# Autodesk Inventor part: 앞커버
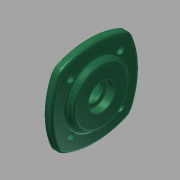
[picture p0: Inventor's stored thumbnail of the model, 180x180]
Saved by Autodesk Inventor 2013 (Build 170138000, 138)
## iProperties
Created: 2015-11
Part Number: 앞커버
Material: 일반
Document SubType Name: Modeling
Designer: mduedu
Density: 2.71 g/cm^3
Author: mduedu
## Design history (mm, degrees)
sketch "스케치1"
  geometry: L1 (50, 50)-(-50, 50); L2 (-50, 50)-(-50, -50); L3 (-50, -50)-(50, -50); L4 (50, -50)-(50, 50); L5 (0, 50)-(0, -50); L6 (50, 0)-(-50, 0); A1 r 90 centre (-40, 0) between (40.415, -40.415) and (40.415, 40.415); A2 r 90 centre (40, 0) between (-40.415, 40.415) and (-40.415, -40.415); A3 r 90 centre (0, -40) between (40.415, 40.415) and (-40.415, 40.415); A4 r 90 centre (0, 40) between (-40.415, -40.415) and (40.415, -40.415); 2 further points
  constraints: 12 end point, 8 point on circle, 5 midpoint, 4 centre point, 2 horizontal alignment, 2 parallel, 2 perpendicular, 2 symmetric about line, 2 tangent, 2 vertical alignment, 1 equal radius, 1 horizontal, 2 other
  dimensions: "d0" = 100 distance of L3.end L1.start; "d2" = 90 radius of A1
extrude "돌출1" new body sketch "스케치1" distance "d3" = 8; taper "d4" = 0 deg
sketch "스케치2"
  geometry: C1 r 35 at (0, 0); 1 further point
  constraints: 1 centre point, 1 coincident
  dimensions: "d5" = 70 diameter of C1
extrude "돌출2" join sketch "스케치2" distance "d6" = 7; taper "d7" = -30 deg
sketch "스케치3"
  geometry: L1 (0, 0)-(0, 40); L2 (0, 0)-(-28.284, 28.284); A1 r 40 centre (0, 0) between (0, 40) and (-28.284, 28.284); 2 further points
  constraints: 4 end point, 2 coincident, 2 point on circle, 1 centre point, 1 vertical
  dimensions: "d8" = 80 diameter of A1; "d9" = 45 deg angle of L1 L2
hole "구멍1" sketch "스케치3" at (-28.284, 28.284) diameter "d11" = 4.5; stored, may be unused: countersink angle "d15" = 90 deg, drill point angle "d17" = 118 deg; dims "d12" = 6, "d13" = 8, "d14" = 4.4, "d16" = 8
sketch "스케치4"
  geometry: C1 r 35 at (0, 0); 1 further point
  constraints: 1 centre point, 1 coincident
  dimensions: "d21" = 70 diameter of C1
extrude "돌출3" join sketch "스케치4" distance "d23" = 12; taper "d24" = 0 deg
hole "구멍2" diameter "d27" = 30; stored, may be unused: countersink angle "d31" = 90 deg, drill point angle "d33" = 0 deg; dims "d25" = 10, "d26" = 10, "d28" = 6, "d29" = 40, "d30" = 12, "d32" = 15
fillet "모깎기2" dims "d35" = 15
fillet "모깎기3" dims "d36" = 3
fillet "모깎기4" dims "d37" = 3
fillet "모깎기5" dims "d38" = 0.3
chamfer "모따기1" distance "d39" = 1; stored, may be unused: second distance "d40" = 2, angle "d41" = 45 deg
hole "구멍3" diameter "d44" = 20; stored, may be unused: countersink angle "d48" = 90 deg, drill point angle "d50" = 118 deg; dims "d45" = 6, "d46" = 30, "d47" = 8.7, "d49" = 8, "d55" = 10, "d56" = 10
fillet "모깎기6" dims "d51" = 0.3
chamfer "모따기2" distance "d52" = 0.7; stored, may be unused: second distance "d53" = 2, angle "d54" = 30 deg
node "솔리드1"
pattern_circular "원형 패턴1" dims angle "d19" = 360 deg
